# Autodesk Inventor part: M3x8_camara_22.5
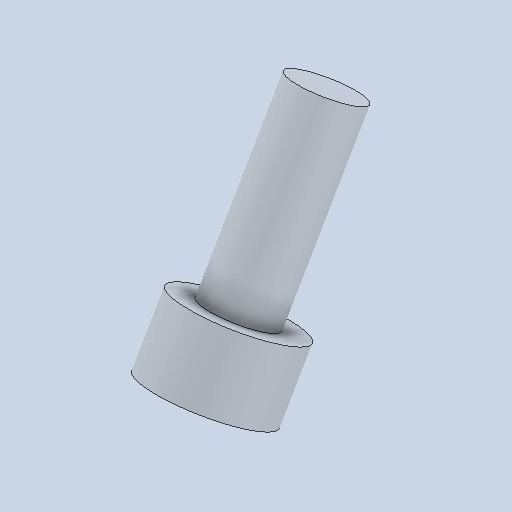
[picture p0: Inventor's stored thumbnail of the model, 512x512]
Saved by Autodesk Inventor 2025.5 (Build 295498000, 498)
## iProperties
Created: 2026-10
Part Number: M3x8_camara_22.5
Material: Genérico
Document SubType Name: Modeling
Designer: Luis M
Density: 1 g/cm^3
Appearance: Valor por defecto
Author: Luis M
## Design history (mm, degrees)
feature "Base1"
node "Sólido1"
